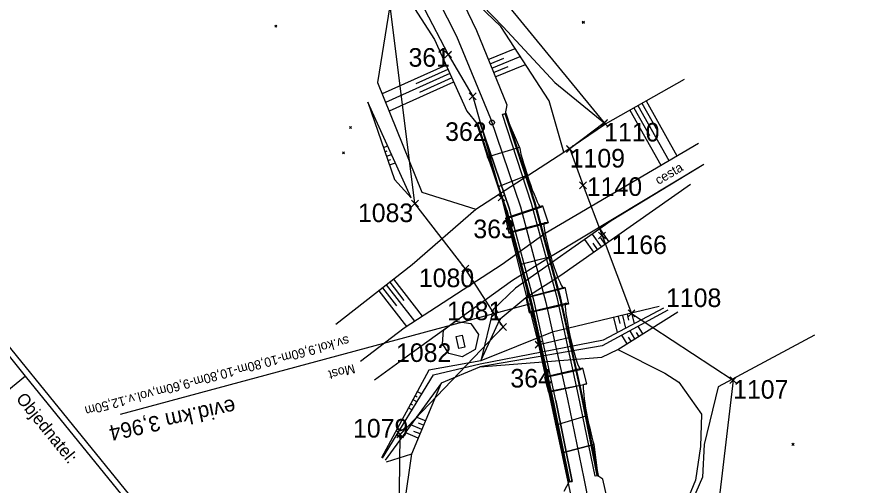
# Model space of a CAD drawing. Extents: x -866402 to -860377, y -1041908 to -1038598.
# Drawn here: x -865502.9 to -865364.2, y -1039888.6 to -1039812.9 of the extents above; entities that cross this region are included whole.
import ezdxf

# ---------------------------------------------------------------- set-up
doc = ezdxf.new("R2010")
doc.units = 0
for name, color, linetype in [('PS 02 trasa', 7, 'Continuous'), ('SZDC', 7, 'Continuous'), ('Vrstva 1', 7, 'Continuous'), ('Vrstva 16', 7, 'Continuous'), ('Vrstva 17', 7, 'Continuous'), ('Vrstva 18', 7, 'Continuous'), ('Vrstva 25', 7, 'Continuous'), ('Vrstva 48', 7, 'Continuous'), ('Vrstva 49', 7, 'Continuous'), ('Vrstva 51', 7, 'Continuous'), ('Vrstva 60', 7, 'Continuous')]:
    doc.layers.add(name, color=color, linetype=linetype)

msp = doc.modelspace()

# ---------------------------------------------------------------- linework, layer by layer
at = {"layer": 'PS 02 trasa'}
msp.add_lwpolyline([(-865628.19, -1039677.88), (-865605.51, -1039687.52), (-865582.19, -1039697.61), (-865559.14, -1039707.28), (-865536.33, -1039717.33), (-865529.82, -1039720.29), (-865517.48, -1039726.61), (-865515.91, -1039727.72), (-865511.27, -1039730.03), (-865496.48, -1039740.5), (-865475.38, -1039758.33), (-865458.86, -1039776.79), (-865444.73, -1039796.94), (-865433.24, -1039818.95), (-865429.29, -1039825.71), (-865424.65, -1039842.04), (-865418.67, -1039865.78), (-865413.42, -1039890.2), (-865408.64, -1039914.82), (-865404.58, -1039939.8), (-865398.64, -1039964), (-865396.05, -1039975.04), (-865392.51, -1039988.18), (-865384.79, -1040012.1)], dxfattribs=at)
at = {"layer": 'SZDC'}
for points in [[(-865395.62, -1040020.69), (-865413.96, -1039944.15), (-865410.47, -1039918.35), (-865441.28, -1039903.04), (-865441.01, -1039880.27), (-865424.37, -1039862.92), (-865425.77, -1039860.85), (-865430.49, -1039853.5), (-865438.62, -1039843), (-865443.16, -1039806.76), (-865453.66, -1039802.74), (-865481.31, -1039769.11), (-865500.26, -1039751.7), (-865548.22, -1039725.62), (-865576.1, -1039709.31), (-865612.95, -1039689.68), (-865615.16, -1039688.82), (-865619.36, -1039687.18)], [(-865431.15, -1039801.77), (-865408.04, -1039829.99), (-865413.61, -1039834.19), (-865411.46, -1039840.07), (-865408.39, -1039848.16), (-865403.62, -1039860.73), (-865387.21, -1039871.5), (-865389.97, -1039894.69), (-865400.05, -1039913.03), (-865396.26, -1039916.02), (-865371.9, -1039915.5), (-865383.99, -1039938.16), (-865384.41, -1039961.48), (-865381.32, -1039975.48), (-865364.16, -1040003.66)]]:
    msp.add_lwpolyline(points, dxfattribs=at)
at = {"layer": 'Vrstva 1'}
for p, q in [((-865541.52, -1039820.25), (-865426.83, -1039961.27)), ((-865501.52, -1039870.84), (-865541.65, -1039821.5)), ((-865501.52, -1039870.84), (-865513.31, -1039880.43)), ((-865461.39, -1039920.18), (-865501.52, -1039870.84))]:
    msp.add_line(p, q, dxfattribs=at)
for points in [[(-865500.16, -1039735.07), (-865487.59, -1039744.45), (-865475.87, -1039754.7), (-865465.13, -1039765.76), (-865455.18, -1039777.66), (-865446.28, -1039790.12), (-865437.99, -1039803.97), (-865431.9, -1039816), (-865426.39, -1039829.26)], [(-865426.39, -1039829.26), (-865421.59, -1039843.56), (-865417.46, -1039858.99), (-865413.96, -1039874.57), (-865411.35, -1039887.39), (-865408.74, -1039900.45)]]:
    msp.add_lwpolyline(points, dxfattribs=at)
msp.add_circle((-865426.17, -1039829.93), 0.4, dxfattribs=at)
at = {"layer": 'Vrstva 16'}
msp.add_lwpolyline([(-865433.99, -1039863.46), (-865432.1, -1039861.99), (-865429.57, -1039862.38), (-865428.35, -1039864.12), (-865428.88, -1039866.55), (-865431.01, -1039867.73), (-865433.13, -1039867.2), (-865434.19, -1039865.62), (-865433.99, -1039863.46)], dxfattribs=at)
at = {"layer": 'Vrstva 17'}
for p, q in [((-865419.33, -1039842.9), (-865424.03, -1039828.55)), ((-865428.61, -1039830.09), (-865423.82, -1039844.08)), ((-865415.18, -1039858.39), (-865419.33, -1039842.9)), ((-865423.82, -1039844.08), (-865419.73, -1039859.55)), ((-865413.11, -1039867.14), (-865415.18, -1039858.39)), ((-865411.73, -1039874.06), (-865413.11, -1039867.14)), ((-865409.16, -1039886.91), (-865411.73, -1039874.06))]:
    msp.add_line(p, q, dxfattribs=at)
msp.add_lwpolyline([(-865419.73, -1039859.55), (-865418.18, -1039866.37), (-865416.21, -1039875.2), (-865413.7, -1039887.79)], dxfattribs=at)
at = {"layer": 'Vrstva 18'}
for p, q in [((-865419.77, -1039843), (-865424.46, -1039828.64)), ((-865421.73, -1039833.91), (-865424.04, -1039828.51)), ((-865424.03, -1039828.51), (-865419.34, -1039842.9)), ((-865424, -1039828.48), (-865419.27, -1039842.9)), ((-865419.21, -1039842.85), (-865423.91, -1039828.46)), ((-865419.21, -1039842.86), (-865423.91, -1039828.48)), ((-865428.67, -1039830.04), (-865423.92, -1039844.1)), ((-865423.87, -1039844.1), (-865428.57, -1039830.01)), ((-865423.78, -1039844.06), (-865428.55, -1039830.12)), ((-865428.55, -1039830.12), (-865426.88, -1039835.48)), ((-865428.51, -1039830.03), (-865423.92, -1039844.07)), ((-865423.37, -1039843.91), (-865428.13, -1039829.85)), ((-865426.88, -1039835.48), (-865421.73, -1039833.91)), ((-865425.11, -1039840.25), (-865420.48, -1039838.4)), ((-865415.6, -1039858.41), (-865419.77, -1039843)), ((-865419.34, -1039842.9), (-865415.19, -1039858.36)), ((-865419.27, -1039842.9), (-865415.1, -1039858.38)), ((-865415.06, -1039858.26), (-865419.21, -1039842.85)), ((-865415.05, -1039858.32), (-865419.21, -1039842.86)), ((-865418.01, -1039843.36), (-865417.12, -1039846.1)), ((-865419.87, -1039859.18), (-865423.92, -1039844.07)), ((-865419.89, -1039859.18), (-865423.92, -1039844.1)), ((-865423.87, -1039844.1), (-865419.84, -1039859.2)), ((-865423.78, -1039845.4), (-865418.27, -1039843.61)), ((-865423.78, -1039844.06), (-865419.72, -1039859.16)), ((-865419.32, -1039859.05), (-865423.37, -1039843.91)), ((-865423.21, -1039847.58), (-865417.69, -1039846.11)), ((-865417.12, -1039846.1), (-865417.69, -1039846.11)), ((-865423.46, -1039847.77), (-865423.21, -1039847.58)), ((-865421.47, -1039852.77), (-865416.66, -1039851.55)), ((-865412.21, -1039873.96), (-865415.6, -1039858.41)), ((-865415.19, -1039858.36), (-865411.75, -1039873.88)), ((-865415.1, -1039858.38), (-865411.71, -1039873.9)), ((-865411.6, -1039873.86), (-865415.06, -1039858.26)), ((-865411.61, -1039873.84), (-865415.05, -1039858.32)), ((-865419.72, -1039859.16), (-865486.23, -1039877.07)), ((-865419.91, -1039860.43), (-865414.27, -1039859.11)), ((-865416.41, -1039875.04), (-865419.89, -1039859.18)), ((-865416.41, -1039875.06), (-865419.87, -1039859.18)), ((-865419.84, -1039859.2), (-865416.33, -1039874.91)), ((-865419.72, -1039859.16), (-865416.26, -1039875.04)), ((-865415.88, -1039874.77), (-865419.32, -1039859.05)), ((-865413.81, -1039859.24), (-865414.27, -1039859.11)), ((-865418.36, -1039865.68), (-865413.53, -1039864.56)), ((-865411.48, -1039869.59), (-865417.69, -1039871.03)), ((-865411.48, -1039869.59), (-865411.87, -1039869.77)), ((-865417.69, -1039871.03), (-865417.07, -1039873.44)), ((-865417.4, -1039871.05), (-865417.69, -1039871.03)), ((-865417.4, -1039871.05), (-865411.87, -1039869.77)), ((-865416.94, -1039873.31), (-865411.36, -1039872.2)), ((-865410.83, -1039872.11), (-865411.36, -1039872.2)), ((-865417.07, -1039873.44), (-865416.94, -1039873.31)), ((-865411.75, -1039873.88), (-865409.1, -1039886.96)), ((-865411.71, -1039873.9), (-865409.03, -1039886.95)), ((-865408.96, -1039886.92), (-865411.61, -1039873.84)), ((-865408.94, -1039886.92), (-865411.6, -1039873.86)), ((-865413.81, -1039887.88), (-865416.41, -1039875.04)), ((-865413.81, -1039887.88), (-865416.41, -1039875.06)), ((-865416.33, -1039874.91), (-865413.7, -1039887.86)), ((-865416.26, -1039875.04), (-865413.66, -1039887.85)), ((-865413.23, -1039887.84), (-865415.88, -1039874.77)), ((-865415.88, -1039874.77), (-865413.21, -1039887.85)), ((-865409.5, -1039887.01), (-865412.21, -1039873.96)), ((-865415.6, -1039878.65), (-865410.82, -1039877.21)), ((-865414.81, -1039883.22), (-865409.71, -1039881.87)), ((-865409.71, -1039881.87), (-865409.1, -1039886.96)), ((-865414.81, -1039883.22), (-865413.69, -1039887.88))]:
    msp.add_line(p, q, dxfattribs=at)
for points in [[(-865424.46, -1039828.64), (-865424, -1039828.48), (-865423.91, -1039828.46), (-865423.91, -1039828.48), (-865424.03, -1039828.51)], [(-865424.03, -1039828.51), (-865424.04, -1039828.51), (-865424.46, -1039828.64)], [(-865428.14, -1039829.85), (-865428.57, -1039830.01), (-865428.67, -1039830.04), (-865428.51, -1039830.03), (-865428.55, -1039830.12)], [(-865428.13, -1039829.85), (-865428.14, -1039829.85), (-865423.37, -1039843.91)], [(-865418.27, -1039843.61), (-865418.01, -1039843.36), (-865423.99, -1039845.38), (-865423.78, -1039845.4)], [(-865423.99, -1039845.38), (-865423.46, -1039847.77), (-865417.12, -1039846.1)], [(-865420.73, -1039858.16), (-865414.4, -1039856.52), (-865413.81, -1039859.24), (-865420.16, -1039860.62)], [(-865420.42, -1039858.16), (-865414.62, -1039856.66), (-865414.4, -1039856.52)], [(-865420.42, -1039858.16), (-865420.73, -1039858.16), (-865420.16, -1039860.62), (-865419.91, -1039860.43)], [(-865417.07, -1039873.44), (-865410.83, -1039872.11), (-865411.48, -1039869.59)], [(-865409.1, -1039886.96), (-865408.96, -1039886.92), (-865408.94, -1039886.92), (-865409.03, -1039886.95), (-865409.5, -1039887.01)], [(-865413.69, -1039887.88), (-865413.66, -1039887.85), (-865413.81, -1039887.88), (-865413.81, -1039887.88), (-865413.7, -1039887.86), (-865413.23, -1039887.84), (-865413.21, -1039887.85), (-865413.69, -1039887.88)]]:
    msp.add_lwpolyline(points, dxfattribs=at)
for centre, major_axis, ratio, start_param, end_param in [((-865420.02, -1039838.42), (-1.73, 5.2), 0.079751, 0.492128, 3.186812), ((-865425.53, -1039840.16), (-1.73, 5.26), 0.067551, 3.200935, 5.78477), ((-865416.14, -1039851.39), (-1.56, 5.28), 0.100382, 6.269575, 9.341514), ((-865421.81, -1039852.87), (-1.4, 5.29), 0.065033, 3.126152, 6.294412), ((-865413.05, -1039864.43), (-1.2, 5.34), 0.089702, 0.045287, 3.102921), ((-865418.64, -1039865.71), (-1.25, 5.34), 0.051171, 3.128508, 6.406752), ((-865410.31, -1039877.49), (-1.05, 5.29), 0.083741, 0.015736, 2.527549), ((-865415.86, -1039878.72), (-1.08, 5.41), 0.048341, 3.724054, 6.295994)]:
    msp.add_ellipse(centre, major_axis=major_axis, ratio=ratio, start_param=start_param, end_param=end_param, dxfattribs=at)
at = {"layer": 'Vrstva 25'}
msp.add_lwpolyline([(-865431.98, -1039864.47), (-865431, -1039864.25), (-865430.56, -1039866.2), (-865431.54, -1039866.42), (-865431.98, -1039864.47)], dxfattribs=at)
at = {"layer": 'Vrstva 48'}
for p, q in [((-865426.78, -1039819.76), (-865422.44, -1039818)), ((-865426.49, -1039820.46), (-865424.26, -1039819.55)), ((-865426.21, -1039821.15), (-865421.6, -1039819.28)), ((-865433.6, -1039820.66), (-865443.94, -1039825.32)), ((-865425.93, -1039821.85), (-865423.56, -1039820.88)), ((-865425.65, -1039822.54), (-865420.77, -1039820.56)), ((-865432.98, -1039822.03), (-865443.37, -1039826.71)), ((-865433.29, -1039821.35), (-865438.47, -1039823.68)), ((-865432.37, -1039823.4), (-865442.81, -1039828.1)), ((-865432.68, -1039822.72), (-865437.88, -1039825.06)), ((-865401.29, -1039826.45), (-865396.31, -1039835.31)), ((-865403.9, -1039827.92), (-865398.89, -1039836.83)), ((-865403.25, -1039827.55), (-865400.75, -1039832)), ((-865402.59, -1039827.18), (-865397.6, -1039836.07)), ((-865401.94, -1039826.81), (-865399.45, -1039831.25)), ((-865443.71, -1039833.94), (-865443.02, -1039833.71)), ((-865443.47, -1039834.65), (-865443.09, -1039834.52)), ((-865443.23, -1039835.36), (-865442.4, -1039835.08)), ((-865442.99, -1039836.07), (-865442.54, -1039835.92)), ((-865442.75, -1039836.78), (-865441.78, -1039836.46)), ((-865407.27, -1039849.12), (-865408.71, -1039847.07)), ((-865409.72, -1039850.85), (-865411.17, -1039848.79)), ((-865408.5, -1039849.98), (-865409.94, -1039847.93)), ((-865407.88, -1039849.55), (-865408.6, -1039848.53)), ((-865409.11, -1039850.42), (-865409.83, -1039849.39)), ((-865442.7, -1039855.68), (-865440.39, -1039858.64)), ((-865442.11, -1039855.22), (-865437.45, -1039861.19)), ((-865444.47, -1039857.07), (-865439.97, -1039862.83)), ((-865443.88, -1039856.6), (-865441.61, -1039859.51)), ((-865443.29, -1039856.14), (-865438.71, -1039862.01)), ((-865406.54, -1039861.4), (-865405.95, -1039863.84)), ((-865405.81, -1039861.23), (-865405.54, -1039862.35)), ((-865405.08, -1039861.05), (-865404.59, -1039863.12)), ((-865404.35, -1039860.88), (-865404.13, -1039861.81)), ((-865403.62, -1039860.7), (-865403.22, -1039862.39)), ((-865403.08, -1039864.82), (-865403.87, -1039863.54)), ((-865402.44, -1039864.43), (-865402.83, -1039863.81)), ((-865401.8, -1039864.03), (-865402.55, -1039862.82)), ((-865404.35, -1039865.62), (-865405.19, -1039864.26)), ((-865403.71, -1039865.22), (-865404.12, -1039864.56)), ((-865438.25, -1039873.33), (-865437.5, -1039873.74)), ((-865438.96, -1039874.65), (-865438.28, -1039875.02)), ((-865438.61, -1039873.99), (-865438.25, -1039874.19)), ((-865439.68, -1039875.97), (-865439.07, -1039876.3)), ((-865439.32, -1039875.31), (-865439, -1039875.49)), ((-865436.93, -1039878.1), (-865438.4, -1039877.49)), ((-865437.51, -1039879.49), (-865439.31, -1039878.74)), ((-865437.22, -1039878.79), (-865438.04, -1039878.45)), ((-865438.09, -1039880.87), (-865440.22, -1039879.98)), ((-865437.8, -1039880.18), (-865438.78, -1039879.77))]:
    msp.add_line(p, q, dxfattribs=at)
at = {"layer": 'Vrstva 49'}
for p, q in [((-865442.23, -1039808.13), (-865444.69, -1039823.48)), ((-865461.28, -1039814.2), (-865460.93, -1039814.55)), ((-865461.28, -1039814.55), (-865460.93, -1039814.2)), ((-865411.58, -1039813.55), (-865411.23, -1039813.91)), ((-865411.58, -1039813.91), (-865411.23, -1039813.55)), ((-865444.69, -1039823.48), (-865437.5, -1039841.16)), ((-865439.24, -1039842.1), (-865446.21, -1039826.63)), ((-865421.73, -1039833.91), (-865424.04, -1039828.51)), ((-865449.22, -1039830.57), (-865448.86, -1039830.92)), ((-865449.22, -1039830.92), (-865448.86, -1039830.57)), ((-865450.34, -1039834.65), (-865449.98, -1039835)), ((-865450.34, -1039835), (-865449.98, -1039834.65)), ((-865437.5, -1039841.16), (-865428.8, -1039843.93)), ((-865428.14, -1039869.37), (-865408.42, -1039867.8)), ((-865434.35, -1039871.92), (-865428.14, -1039869.37)), ((-865436.38, -1039869.88), (-865444.04, -1039884.04)), ((-865443.85, -1039884.1), (-865435.6, -1039870.65)), ((-865434.35, -1039871.92), (-865443.44, -1039884.42)), ((-865439.14, -1039883.39), (-865434.35, -1039871.92)), ((-865377.73, -1039881.68), (-865377.38, -1039882.03)), ((-865377.73, -1039882.03), (-865377.38, -1039881.68)), ((-865443.21, -1039884.67), (-865439.14, -1039883.39)), ((-865408.25, -1039887.48), (-865409.1, -1039886.96)), ((-865413.69, -1039887.88), (-865414.58, -1039889.5))]:
    msp.add_line(p, q, dxfattribs=at)
for points in [[(-865435.52, -1039802.61), (-865432.2, -1039807.77), (-865428.69, -1039815.06), (-865423.8, -1039827.07), (-865424.04, -1039828.51)], [(-865414.54, -1039834.69), (-865416.94, -1039826.44), (-865424.74, -1039814.45), (-865431.91, -1039807.52), (-865435.52, -1039802.61)], [(-865434.9, -1039802.36), (-865431.14, -1039807.42), (-865424.35, -1039814.48), (-865416, -1039823.48), (-865407.83, -1039830.12)], [(-865441.32, -1039807.36), (-865435.47, -1039816.52), (-865430.26, -1039828.07), (-865428.55, -1039830.12)], [(-865428.8, -1039843.93), (-865414.54, -1039834.69), (-865407.83, -1039830.12), (-865395.05, -1039822.94)], [(-865446.21, -1039826.63), (-865441.94, -1039839.14), (-865439.24, -1039842.1)], [(-865428.55, -1039830.12), (-865426.88, -1039835.48), (-865421.73, -1039833.91)], [(-865447.41, -1039868.47), (-865440.37, -1039863.09), (-865424.53, -1039852.77), (-865417.56, -1039847.81), (-865392.8, -1039833.25)], [(-865391.97, -1039836.73), (-865406.9, -1039845.79), (-865422.36, -1039856.68), (-865426, -1039860.09), (-865427.96, -1039868.39)], [(-865427.96, -1039868.39), (-865424.84, -1039861.6), (-865420.73, -1039858.16), (-865415.03, -1039854.57), (-865394.11, -1039839.88)], [(-865451.38, -1039862.47), (-865439.07, -1039852.84), (-865428.8, -1039843.93)], [(-865399.19, -1039859.64), (-865416.43, -1039863.76), (-865427.96, -1039868.39), (-865436.38, -1039869.88)], [(-865435.6, -1039870.65), (-865428.06, -1039868.89), (-865408.15, -1039865.01), (-865398.4, -1039859.82)], [(-865397.74, -1039860.2), (-865408.36, -1039865.99), (-865428.14, -1039869.37)], [(-865408.42, -1039867.8), (-865405.86, -1039866.56), (-865396.14, -1039860.5)], [(-865374.06, -1039864.27), (-865389.62, -1039872.56), (-865391.89, -1039881.91), (-865392.17, -1039887.18), (-865403.19, -1039912.57)], [(-865405.86, -1039866.56), (-865398.24, -1039870.36), (-865396, -1039871.86), (-865392.31, -1039877.02), (-865392.46, -1039882.21), (-865393.28, -1039887.63), (-865403.14, -1039911.55), (-865403.68, -1039912.79)], [(-865409.1, -1039886.96), (-865409.71, -1039881.87), (-865414.81, -1039883.22), (-865413.69, -1039887.88)], [(-865449.86, -1039908.89), (-865439.38, -1039901.87), (-865440.29, -1039891.65), (-865439.14, -1039883.39)], [(-865403.68, -1039912.79), (-865403.46, -1039908.59), (-865408.25, -1039887.48)]]:
    msp.add_lwpolyline(points, dxfattribs=at)
at = {"layer": 'Vrstva 51'}
for points in [[(-865447.41, -1039868.47), (-865440.37, -1039863.09), (-865424.53, -1039852.77), (-865417.56, -1039847.81), (-865392.8, -1039833.25)], [(-865391.97, -1039836.73), (-865416.45, -1039851.46), (-865422.88, -1039855.4), (-865438.07, -1039866.37), (-865445.15, -1039871.5)]]:
    msp.add_lwpolyline(points, dxfattribs=at)
at = {"layer": 'Vrstva 60'}
for p, q in [((-865432.79, -1039819.4), (-865433.79, -1039818.4)), ((-865433.69, -1039819.4), (-865432.69, -1039818.4)), ((-865432.79, -1039818.5), (-865433.79, -1039819.5)), ((-865433.69, -1039818.5), (-865432.69, -1039819.5)), ((-865433.24, -1039818.95), (-865433.24, -1039818.95)), ((-865428.84, -1039826.16), (-865429.84, -1039825.16)), ((-865428.84, -1039825.26), (-865429.84, -1039826.26)), ((-865429.74, -1039826.16), (-865428.74, -1039825.16)), ((-865429.74, -1039825.26), (-865428.74, -1039826.26)), ((-865429.29, -1039825.71), (-865429.29, -1039825.71)), ((-865407.59, -1039830.44), (-865408.59, -1039829.44)), ((-865408.49, -1039830.44), (-865407.49, -1039829.44)), ((-865407.59, -1039829.54), (-865408.59, -1039830.54)), ((-865408.49, -1039829.54), (-865407.49, -1039830.54)), ((-865408.04, -1039829.99), (-865408.04, -1039829.99)), ((-865413.16, -1039834.64), (-865414.16, -1039833.64)), ((-865414.06, -1039834.64), (-865413.06, -1039833.64)), ((-865413.16, -1039833.74), (-865414.16, -1039834.74)), ((-865414.06, -1039833.74), (-865413.06, -1039834.74)), ((-865413.61, -1039834.19), (-865413.61, -1039834.19)), ((-865411.01, -1039840.52), (-865412.01, -1039839.52)), ((-865411.01, -1039839.62), (-865412.01, -1039840.62)), ((-865411.91, -1039840.52), (-865410.91, -1039839.52)), ((-865411.91, -1039839.62), (-865410.91, -1039840.62)), ((-865411.46, -1039840.07), (-865411.46, -1039840.07)), ((-865424.2, -1039842.49), (-865425.2, -1039841.49)), ((-865424.2, -1039841.59), (-865425.2, -1039842.59)), ((-865425.1, -1039842.49), (-865424.1, -1039841.49)), ((-865425.1, -1039841.59), (-865424.1, -1039842.59)), ((-865438.17, -1039843.45), (-865439.17, -1039842.45)), ((-865438.17, -1039842.55), (-865439.17, -1039843.55)), ((-865439.07, -1039843.45), (-865438.07, -1039842.45)), ((-865439.07, -1039842.55), (-865438.07, -1039843.55)), ((-865438.62, -1039843), (-865438.62, -1039843)), ((-865424.65, -1039842.04), (-865424.65, -1039842.04)), ((-865407.94, -1039848.61), (-865408.94, -1039847.61)), ((-865407.94, -1039847.71), (-865408.94, -1039848.71)), ((-865408.84, -1039848.61), (-865407.84, -1039847.61)), ((-865408.84, -1039847.71), (-865407.84, -1039848.71)), ((-865408.39, -1039848.16), (-865408.39, -1039848.16)), ((-865430.04, -1039853.95), (-865431.04, -1039852.95)), ((-865430.04, -1039853.05), (-865431.04, -1039854.05)), ((-865430.94, -1039853.95), (-865429.94, -1039852.95)), ((-865430.94, -1039853.05), (-865429.94, -1039854.05)), ((-865430.49, -1039853.5), (-865430.49, -1039853.5)), ((-865425.32, -1039861.3), (-865426.32, -1039860.3)), ((-865425.32, -1039860.4), (-865426.32, -1039861.4)), ((-865426.22, -1039861.3), (-865425.22, -1039860.3)), ((-865426.22, -1039860.4), (-865425.22, -1039861.4)), ((-865425.77, -1039860.85), (-865425.77, -1039860.85)), ((-865403.17, -1039861.18), (-865404.17, -1039860.18)), ((-865403.17, -1039860.28), (-865404.17, -1039861.28)), ((-865404.07, -1039861.18), (-865403.07, -1039860.18)), ((-865404.07, -1039860.28), (-865403.07, -1039861.28)), ((-865403.62, -1039860.73), (-865403.62, -1039860.73)), ((-865423.92, -1039863.37), (-865424.92, -1039862.37)), ((-865423.92, -1039862.47), (-865424.92, -1039863.47)), ((-865424.82, -1039863.37), (-865423.82, -1039862.37)), ((-865424.82, -1039862.47), (-865423.82, -1039863.47)), ((-865424.37, -1039862.92), (-865424.37, -1039862.92)), ((-865418.22, -1039866.22), (-865419.22, -1039865.22)), ((-865418.22, -1039865.33), (-865419.22, -1039866.33)), ((-865419.12, -1039866.22), (-865418.12, -1039865.22)), ((-865419.12, -1039865.33), (-865418.12, -1039866.33)), ((-865418.67, -1039865.78), (-865418.67, -1039865.78)), ((-865386.76, -1039871.95), (-865387.76, -1039870.95)), ((-865386.76, -1039871.05), (-865387.76, -1039872.05)), ((-865387.66, -1039871.95), (-865386.66, -1039870.95)), ((-865387.66, -1039871.05), (-865386.66, -1039872.05)), ((-865387.21, -1039871.5), (-865387.21, -1039871.5)), ((-865440.56, -1039880.72), (-865441.56, -1039879.72)), ((-865440.56, -1039879.82), (-865441.56, -1039880.82)), ((-865441.46, -1039880.72), (-865440.46, -1039879.72)), ((-865441.46, -1039879.82), (-865440.46, -1039880.82)), ((-865441.01, -1039880.27), (-865441.01, -1039880.27))]:
    msp.add_line(p, q, dxfattribs=at)

# ---------------------------------------------------------------- texts
at = {"layer": 'Vrstva 1'}
msp.add_text('Objednatel:', height=2, rotation=309.124, dxfattribs=at).set_placement((-865503.17, -1039874.55))
at = {"layer": 'Vrstva 18'}
for s, height, rotation, p in [('sv.kol.9,60m-10,80m-10,80m-9,60m,vol.v.12,50m', 1.5, 195.0736, (-865449.46, -1039864.34)), ('Most', 1.5, 195.0736, (-865448.53, -1039868.88)), ('evid.km 3,964', 2.5, 192.2814, (-865467.9, -1039874.48))]:
    msp.add_text(s, height=height, rotation=rotation, dxfattribs=at).set_placement(p)
at = {"layer": 'Vrstva 51'}
msp.add_text('cesta', height=1.5, rotation=30.464, dxfattribs=at).set_placement((-865399.27, -1039840.02))
at = {"layer": 'Vrstva 60'}
for s, p in [('361', (-865439.66, -1039820.92)), ('362', (-865433.74, -1039832.9)), ('1110', (-865408.04, -1039832.99)), ('1109', (-865413.61, -1039837.19)), ('1140', (-865410.84, -1039841.77)), ('1083', (-865447.83, -1039846)), ('363', (-865429.18, -1039848.6)), ('1166', (-865406.84, -1039851.16)), ('1080', (-865437.98, -1039856.5)), ('1108', (-865398.05, -1039859.71)), ('1081', (-865433.44, -1039861.83)), ('1082', (-865441.67, -1039868.57)), ('364', (-865423.2, -1039872.7)), ('1107', (-865387.21, -1039874.5)), ('1079', (-865448.62, -1039880.77))]:
    msp.add_text(s, height=3, dxfattribs=at).set_placement(p)

doc.saveas('drawing.dxf')
